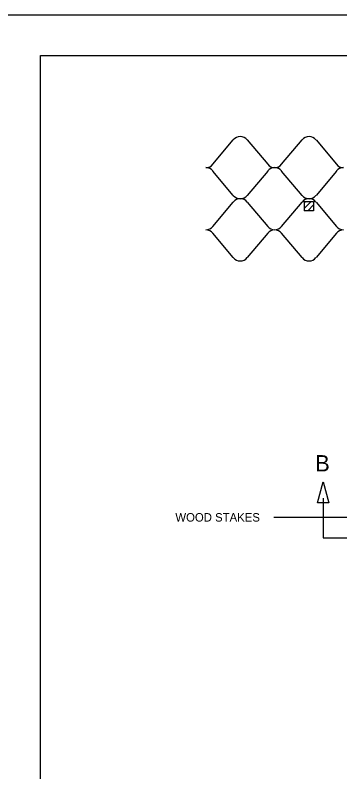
# Model space of a CAD drawing. Extents: x 638850 to 644908, y 297188 to 298900.
# Drawn here: x 641302.5 to 641411, y 297618.5 to 297871.3 of the extents above; entities that cross this region are included whole.
import ezdxf

# ---------------------------------------------------------------- set-up
doc = ezdxf.new("R2010")
doc.units = 0
for name, color, linetype in [('1', 7, 'Continuous'), ('3', 7, 'Continuous'), ('4', 7, 'Continuous'), ('5', 7, 'Continuous'), ('6', 7, 'Continuous')]:
    doc.layers.add(name, color=color, linetype=linetype)

msp = doc.modelspace()

# ---------------------------------------------------------------- linework, layer by layer
at = {"layer": '1'}
for p, q in [((642242.46, 297871.34), (641270.46, 297871.34)), ((641310.96, 297290.55), (641310.96, 297857.84)), ((641310.96, 297857.84), (642228.96, 297857.84))]:
    msp.add_line(p, q, dxfattribs=at)
at = {"layer": '4'}
for p, q in [((641368.54, 297821.49), (641375.37, 297829.65)), ((641380.02, 297829.65), (641386.86, 297821.49)), ((641391.5, 297821.49), (641398.34, 297829.65)), ((641402.99, 297829.65), (641409.82, 297821.49)), ((641375.37, 297811.1), (641368.54, 297819.26)), ((641386.86, 297819.26), (641380.02, 297811.1)), ((641398.34, 297811.1), (641391.5, 297819.26)), ((641409.82, 297819.26), (641402.99, 297811.1)), ((641368.54, 297800.71), (641375.37, 297808.88)), ((641380.02, 297808.88), (641386.86, 297800.71)), ((641391.5, 297800.71), (641398.34, 297808.88)), ((641402.99, 297808.88), (641409.82, 297800.71)), ((641375.37, 297790.32), (641368.54, 297798.49)), ((641386.86, 297798.49), (641380.02, 297790.32)), ((641398.34, 297790.32), (641391.5, 297798.49)), ((641409.82, 297798.49), (641402.99, 297790.32))]:
    msp.add_line(p, q, dxfattribs=at)
for centre, start, end in [((641377.7, 297827.77), 90, 141.0518), ((641377.7, 297827.77), 38.9482, 90), ((641400.66, 297827.77), 90, 141.0518), ((641400.66, 297827.77), 38.9482, 90), ((641366.22, 297823.37), 270, 321.0518), ((641366.22, 297817.39), 38.9482, 90), ((641389.18, 297823.37), 218.9482, 270), ((641389.18, 297817.39), 90, 141.0518), ((641389.18, 297823.37), 270, 321.0518), ((641389.18, 297817.39), 38.9482, 90), ((641412.14, 297823.37), 218.9482, 270), ((641412.14, 297817.39), 90, 141.0518), ((641377.7, 297812.98), 218.9482, 270), ((641377.7, 297807), 90, 141.0518), ((641377.7, 297812.98), 270, 321.0518), ((641377.7, 297807), 38.9482, 90), ((641400.66, 297812.98), 218.9482, 270), ((641400.66, 297807), 90, 141.0518), ((641400.66, 297812.98), 270, 321.0518), ((641400.66, 297807), 38.9482, 90), ((641366.22, 297802.59), 270, 321.0518), ((641366.22, 297796.61), 38.9482, 90), ((641389.18, 297802.59), 218.9482, 270), ((641389.18, 297796.61), 90, 141.0518), ((641389.18, 297802.59), 270, 321.0518), ((641389.18, 297796.61), 38.9482, 90), ((641412.14, 297802.59), 218.9482, 270), ((641412.14, 297796.61), 90, 141.0518), ((641377.7, 297792.2), 218.9482, 270), ((641377.7, 297792.2), 270, 321.0518), ((641400.66, 297792.2), 218.9482, 270), ((641400.66, 297792.2), 270, 321.0518)]:
    msp.add_arc(centre, 2.99, start, end, dxfattribs=at)
at = {"layer": '5'}
for p, q in [((641405.39, 297710), (641405.39, 297696.7)), ((641388.86, 297703.65), (641444.61, 297703.65)), ((641405.39, 297696.7), (641601.73, 297696.7))]:
    msp.add_line(p, q, dxfattribs=at)
msp.add_lwpolyline([(641403.47, 297708.36), (641405.36, 297715.38), (641407.25, 297708.36)], close=True, dxfattribs=at)
at = {"layer": '6'}
for p, q in [((641399.08, 297809.05), (641402.18, 297809.05)), ((641399.08, 297809.05), (641399.08, 297805.99)), ((641399.08, 297806.77), (641401.36, 297809.05)), ((641399.08, 297808.7), (641399.43, 297809.05)), ((641402.18, 297809.05), (641402.18, 297805.99)), ((641400.23, 297805.99), (641402.18, 297807.94)), ((641402.18, 297805.99), (641399.08, 297805.99)), ((641402.17, 297805.99), (641402.18, 297806))]:
    msp.add_line(p, q, dxfattribs=at)

# ---------------------------------------------------------------- texts
at = {"layer": '3'}
msp.add_text('WOOD STAKES', height=2.835, dxfattribs=at).set_placement((641356.02, 297702.12))
at = {"layer": '5'}
msp.add_text('B', height=5.45, dxfattribs=at).set_placement((641402.72, 297718.88))

doc.saveas('drawing.dxf')
